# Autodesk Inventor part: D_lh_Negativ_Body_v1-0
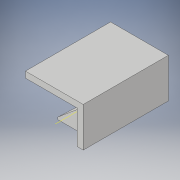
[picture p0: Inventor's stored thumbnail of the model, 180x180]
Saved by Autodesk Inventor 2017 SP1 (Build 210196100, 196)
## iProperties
Part Number: D_lh_Negativ_Body_v1-0
Material: Generisch
Document SubType Name: Modeling
Designer: haesner
Density: 1 g/cm^3
Appearance: Vorgabe
Part Number: D_lh_Negativ_Body_v1-0_3D-Druck
Author: haesner
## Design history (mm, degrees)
sketch "Skizze1"
  geometry: L1 (0, 9.5)-(-2, 9.5); L2 (-2, 9.5)-(-10.86, -9.5); L3 (-10.86, -9.5)-(0, -9.5); L4 (0, -9.5)-(0, 9.5); L5 (0, -13.3)-(0, 13.3) reference; L6 (-13.032, 0)-(2.172, 0) reference; 1 further point
  constraints: 8 end point, 1 collinear, 1 horizontal, 1 parallel, 1 perpendicular, 1 other
  dimensions: "d0" = 2 distance of L1.start L1.end; "d1" = 25 deg angle of L2 L4; "d2" = 19 distance of L3.end L1.start
extrude "Extrusion1" new body sketch "Skizze1" distance "d3" = 9; taper "d4" = 0 deg
sketch "Skizze2"
  geometry: L1 (-1, 12.579)-(-1, -17.12); L2 (0, -23.059)-(0, 18.519) reference; 1 further point
  constraints: 2 end point, 1 vertical
  dimensions: "d5" = 1 distance between parallel lines of L2 L1
workplane "Arbeitsebene1"
  workaxis "Arbeitsachse1"
feature "Trennen1"
sketch "Skizze3"
  geometry: L1 (-1, 9.5)-(-1, -9.5) reference; L2 (-1, -9.5)-(0, -9.5) reference; L3 (0, -9.5)-(0, 9.5) reference; L4 (0, 9.5)-(-1, 9.5) reference; 1 further point
extrude "Extrusion2" join sketch "Skizze3" distance "d7" = 1; taper "d8" = 0 deg
sketch "Skizze4"
  geometry: L1 (-2, 9.5)-(-1, 9.5) reference; L2 (0, 9.5)-(-1, 9.5) reference; L3 (0, -9.5)-(0, 9.5) reference; L4 (-1, -9.5)-(0, -9.5) reference; L5 (-1, -9.5)-(-10.86, -9.5) reference; L6 (-10.86, -9.5)-(-2, 9.5) reference; 1 further point
extrude "Extrusion3" join sketch "Skizze4" distance "d9" = 1; taper "d10" = 0 deg
sketch "Skizze5"
  geometry: L1 (0, 14)-(-17, 14); L2 (-17, 14)-(-17, -14); L3 (-17, -14)-(0, -14); L4 (0, -14)-(0, 14); L5 (0, -23.744)-(0, 22.624) reference; L6 (-20.4, 0)-(3.4, 0) reference; 1 further point
  constraints: 8 end point, 2 parallel, 1 collinear, 1 horizontal, 1 perpendicular, 1 other
  dimensions: "d11" = 28 distance of L3.end L1.start; "d12" = 17 distance of L1.start L1.end
extrude "Extrusion4" join sketch "Skizze5" distance "d13" = 2; taper "d14" = 0 deg
sketch "Skizze6"
  geometry: L1 (-11, 23.5)-(-13, 23.5) reference; L2 (-11, -4.5)-(-13, -4.5) reference; L3 (-11, 23.5)-(-11, 23.5); L4 (-11, 23.5)-(0, 23.5); L5 (0, 23.5)-(0, -4.5); L6 (0, -4.5)-(-11, -4.5); L7 (-11, -4.5)-(-11, -4.5); L8 (-13, -4.5)-(-13, 23.5) reference; L9 (2.6, 9.5)-(-15.6, 9.5) reference; L10 (0, -14.244)-(0, 32.124) reference; L11 (-11, 19)-(-11, 23.5) reference; L12 (-11, -4.5)-(-11, 0) reference; 1 further point
  constraints: 10 end point, 2 collinear, 2 perpendicular, 1 parallel, 1 other
  dimensions: "d15" = 28 distance of L4.end L5.end
extrude "Extrusion5" join sketch "Skizze6" distance "d16" = 2; taper "d17" = 0 deg
node "Volumenkörper1"
node "Projizierte Kontur1"
other parameters: "d6" = 40 deg
